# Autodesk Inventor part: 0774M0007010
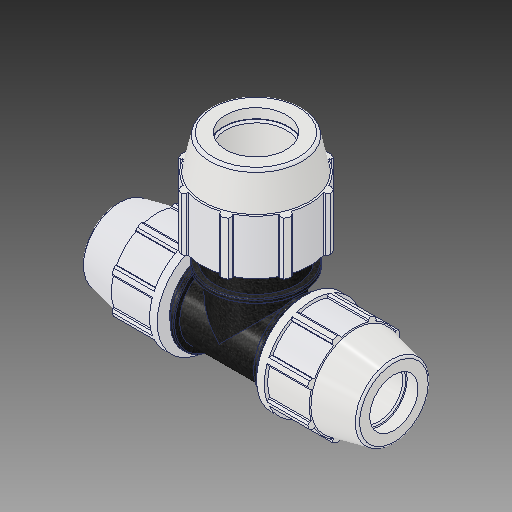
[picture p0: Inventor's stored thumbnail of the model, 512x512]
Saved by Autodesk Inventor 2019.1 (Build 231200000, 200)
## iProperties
Created: 2017-02
Part Number: 0774M0007010
Material: PVC-Piping
Description: Plasson Enlarging Tee 90 3/4'' - 1'' - 3/4''
Document SubType Name: Modeling
Designer: KIM
Mass: 92.6774 g
Surface Area: 199.44 cm^2
Volume: 66.1981 cm^3
Density: 1.4 g/cm^3
Appearance: PTFE
Author: KIM
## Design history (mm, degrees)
derived "0774M0.ipt"
feature "Solid1::0774M0.ipt"
tag "TaggingFeature1"
body "Solid1"
other parameters: "d2" = 26.6, "d4" = 7.57767, "d5" = 21.26488, "d7" = 54.102, "d9" = 12.99029, "d11" = 2.53153, "d13" = 120 deg, "d14" = 39.9, "d15" = 12 deg, "d16" = 47.06874, "d18" = 1.33, "d19" = 35 deg, "d20" = 17.5 deg, "d21" = 50.31486, "d23" = 0, "d25" = 360 deg, "d27" = 1.08204, "d33" = 0.532, "d42" = 27.34056, "d43" = 1.62306, "d46" = 0.798, "d67" = 40.5765, "d76" = 33.3, "d77" = 64.008, "d78" = 12 deg, "d79" = 90.932, "d80" = 120 deg, "d81" = 49.95, "d82" = 6.25, "d85" = 40.5765, "d87" = 2.5, "d89" = 18.75, "d96" = 6.32883, "d98" = 59.52744, "d99" = 35 deg, "d100" = 17.5 deg, "d102" = 0, "d103" = 1.28016, "d107" = 360 deg, "d109" = 0.999, "d112" = 1.665, "d113" = 4.2672, "d114" = 0, "d117" = 151.892, "d118" = 51.2064, "d126" = 23.94, "d127" = 58.928, "d131" = 12.73048, "d132" = 23.94, "d133" = 65.024, "d135" = 0, "d138" = 3.03784, "d139" = 44.8056, "d141" = 0, "d143" = 0, "d147" = 0, "d_" = 26.6, "E_" = 54.102, "A_" = 90.932, "l_" = 58.928, "E_1" = 64.008, "l_1" = 65.024, "A_1" = 75, "d_1" = 33.3, "H_" = 151.892
